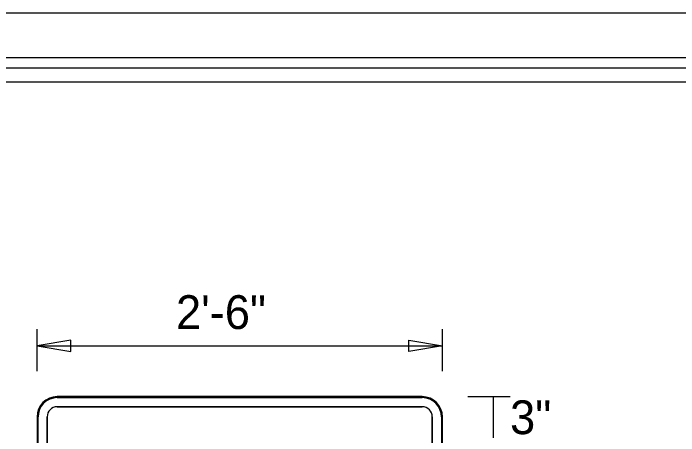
# Model space of a CAD drawing. Extents: x 17890628 to 17890844, y 17897693 to 17898031.
# Drawn here: x 17890745.88 to 17890759.01, y 17897991.48 to 17897999.81 of the extents above; entities that cross this region are included whole.
import ezdxf

# ---------------------------------------------------------------- set-up
doc = ezdxf.new("R2010")
doc.units = 0
for name, color, linetype in [('GSColorFill', 7, 'Continuous'), ('GSDims', 7, 'Continuous'), ('GSOutline', 7, 'Continuous'), ('PlotBorder_dp', 7, 'Continuous'), ('SheetBorder_dp', 7, 'Continuous'), ('SheetLinesMisc2_dp', 7, 'Continuous')]:
    doc.layers.add(name, color=color, linetype=linetype)

msp = doc.modelspace()

# ---------------------------------------------------------------- linework, layer by layer
at = {"layer": 'GSColorFill'}
for p, q in [((17890753.95, 17897992.247), (17890746.75, 17897992.247)), ((17890753.95, 17897992.247), (17890746.75, 17897992.247)), ((17890753.95, 17897992.247), (17890746.75, 17897992.247)), ((17890746.75, 17897992.227), (17890753.95, 17897992.227)), ((17890746.75, 17897992.047), (17890753.95, 17897992.047)), ((17890746.35, 17897991.847), (17890746.35, 17897983.047)), ((17890746.35, 17897991.847), (17890746.35, 17897983.047)), ((17890746.35, 17897991.847), (17890746.35, 17897983.047)), ((17890746.37, 17897983.047), (17890746.37, 17897991.847)), ((17890746.55, 17897983.047), (17890746.55, 17897991.847)), ((17890754.15, 17897991.847), (17890754.15, 17897983.047)), ((17890754.33, 17897991.847), (17890754.33, 17897983.047)), ((17890754.35, 17897983.047), (17890754.35, 17897991.847)), ((17890754.35, 17897983.047), (17890754.35, 17897991.847)), ((17890754.35, 17897983.047), (17890754.35, 17897991.847))]:
    msp.add_line(p, q, dxfattribs=at)
for centre, radius, start, end in [((17890746.75, 17897991.847), 0.4, 90, 180), ((17890746.75, 17897991.847), 0.4, 90, 180), ((17890746.75, 17897991.847), 0.4, 90, 180), ((17890746.75, 17897991.847), 0.38, 90, 180), ((17890753.95, 17897991.847), 0.4, 360, 90), ((17890753.95, 17897991.847), 0.4, 360, 90), ((17890753.95, 17897991.847), 0.4, 0, 90), ((17890753.95, 17897991.847), 0.38, 0, 90), ((17890746.75, 17897991.847), 0.2, 90, 180), ((17890753.95, 17897991.847), 0.2, 360, 90)]:
    msp.add_arc(centre, radius, start, end, dxfattribs=at)
at = {"layer": 'GSDims'}
for p, q in [((17890746.35, 17897992.747), (17890746.35, 17897993.581)), ((17890754.35, 17897992.747), (17890754.35, 17897993.581)), ((17890746.35, 17897993.247), (17890754.35, 17897993.247)), ((17890754.85, 17897992.247), (17890755.684, 17897992.247)), ((17890755.35, 17897992.247), (17890755.35, 17897991.434))]:
    msp.add_line(p, q, dxfattribs=at)
for points in [[(17890746.35, 17897993.247), (17890747.017, 17897993.136), (17890747.017, 17897993.358)], [(17890754.35, 17897993.247), (17890753.684, 17897993.136), (17890753.684, 17897993.358)]]:
    msp.add_lwpolyline(points, close=True, dxfattribs=at)
at = {"layer": 'GSOutline'}
for p, q in [((17890753.95, 17897992.247), (17890746.75, 17897992.247)), ((17890753.95, 17897992.047), (17890746.75, 17897992.047)), ((17890746.35, 17897991.847), (17890746.35, 17897983.047)), ((17890746.55, 17897991.847), (17890746.55, 17897983.047)), ((17890754.15, 17897983.047), (17890754.15, 17897991.847)), ((17890754.35, 17897983.047), (17890754.35, 17897991.847))]:
    msp.add_line(p, q, dxfattribs=at)
for centre, radius, start, end in [((17890746.75, 17897991.847), 0.4, 90, 180), ((17890753.95, 17897991.847), 0.4, 360, 90), ((17890746.75, 17897991.847), 0.2, 90, 180), ((17890753.95, 17897991.847), 0.2, 360, 90)]:
    msp.add_arc(centre, radius, start, end, dxfattribs=at)
at = {"layer": 'PlotBorder_dp'}
msp.add_lwpolyline([(17890700.471, 17897907.61), (17890843.989, 17897907.61), (17890843.989, 17897999.809), (17890700.471, 17897999.809)], close=True, dxfattribs=at)
at = {"layer": 'SheetBorder_dp'}
msp.add_line((17890705.254, 17897998.94), (17890839.205, 17897998.94), dxfattribs=at)
at = {"layer": 'SheetLinesMisc2_dp'}
for p, q in [((17890705.5, 17897998.732), (17890839.233, 17897998.732)), ((17890726.429, 17897998.455), (17890771.912, 17897998.455))]:
    msp.add_line(p, q, dxfattribs=at)

# ---------------------------------------------------------------- texts
at = {"layer": 'GSDims'}
for s, p in [('2\'-6"', (17890749.093, 17897993.581)), ('3"', (17890755.684, 17897991.507))]:
    msp.add_text(s, height=0.6667, dxfattribs=at).set_placement(p)

doc.saveas('drawing.dxf')
